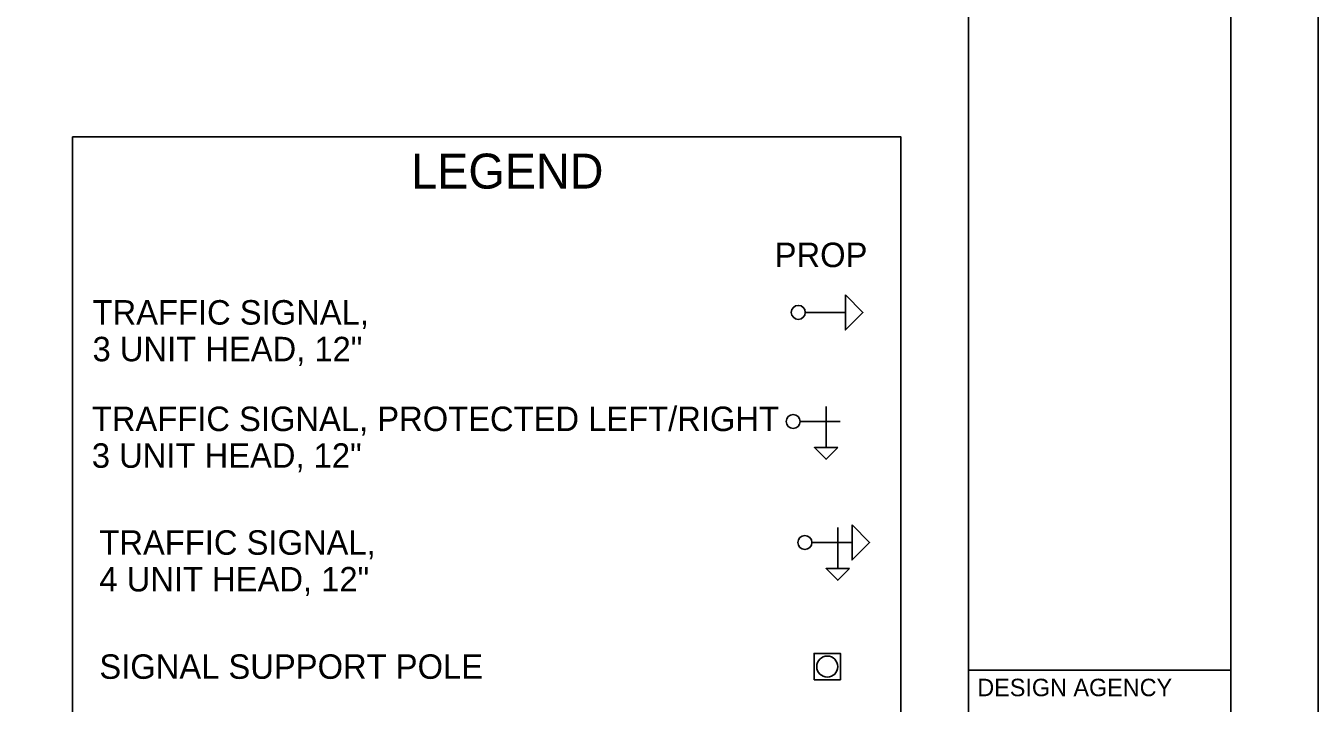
# Model space of a CAD drawing. Extents: x 0 to 34, y 0 to 22.
# Drawn here: x 26.61 to 34, y 4.31 to 8.19 of the extents above; entities that cross this region are included whole.
import ezdxf

# ---------------------------------------------------------------- set-up
doc = ezdxf.new("R2010")
doc.units = 0
for name, color, linetype in [('PM_P_Stop_Line', 7, 'Continuous'), ('SC_Scratch1', 7, 'Continuous'), ('SG_P_Detection', 7, 'Continuous'), ('SG_P_Heads', 7, 'Continuous'), ('UT_X_Electric', 7, 'Continuous')]:
    doc.layers.add(name, color=color, linetype=linetype)

msp = doc.modelspace()

# ---------------------------------------------------------------- linework, layer by layer
at = {"layer": 'PM_P_Stop_Line'}
for p, q in [((32, 0.5), (32, 21.5)), ((32, 4.5), (33.5, 4.5))]:
    msp.add_line(p, q, dxfattribs=at)
msp.add_lwpolyline([(1.5, 21.5), (33.5, 21.5), (33.5, 0.5), (1.5, 0.5)], close=True, dxfattribs=at)
at = {"layer": 'SC_Scratch1'}
msp.add_lwpolyline([(26.8738, 7.5516), (26.8738, 0.8263), (31.6119, 0.8263), (31.612, 7.5516), (31.612, 7.5516)], close=True, dxfattribs=at)
at = {"layer": 'SG_P_Detection'}
for p, q in [((31.1856, 6.0076), (31.1849, 5.7726)), ((31.0361, 5.9223), (31.2661, 5.9215))]:
    msp.add_line(p, q, dxfattribs=at)
msp.add_lwpolyline([(31.2513, 5.7727), (31.1844, 5.7062), (31.1179, 5.7731)], close=True, dxfattribs=at)
msp.add_circle((30.9961, 5.9224), 0.04, dxfattribs=at)
at = {"layer": 'SG_P_Heads'}
msp.add_lwpolyline([(0, 0), (34, 0), (34, 22), (0, 22)], close=True, dxfattribs=at)
at = {"layer": 'UT_X_Electric'}
for p, q in [((31.0658, 6.5467), (31.2958, 6.5467)), ((31.2528, 5.3154), (31.2528, 5.0804)), ((31.1036, 5.2295), (31.3336, 5.2295))]:
    msp.add_line(p, q, dxfattribs=at)
for points in [[(31.2957, 6.6466), (31.3957, 6.5466), (31.2957, 6.4466)], [(31.3331, 5.3299), (31.4331, 5.2299), (31.3331, 5.1299)], [(31.3184, 5.0807), (31.2518, 5.014), (31.1851, 5.0807)], [(31.1165, 4.4445), (31.2665, 4.4445), (31.2665, 4.5945), (31.1165, 4.5945)]]:
    msp.add_lwpolyline(points, close=True, dxfattribs=at)
for centre, radius in [((31.0258, 6.5467), 0.04), ((31.0636, 5.2295), 0.04), ((31.1915, 4.5195), 0.06)]:
    msp.add_circle(centre, radius, dxfattribs=at)

# ---------------------------------------------------------------- texts
at = {"layer": 'SC_Scratch1'}
msp.add_text('DESIGN AGENCY', height=0.1, dxfattribs=at).set_placement((32.05, 4.35))
at = {"layer": 'UT_X_Electric'}
for s, height, p in [('LEGEND', 0.2, (28.8111, 7.255)), ('PROP', 0.14, (30.8906, 6.8056)), ('TRAFFIC SIGNAL, ', 0.14, (26.9879, 6.4767)), ('3 UNIT HEAD, 12"', 0.14, (26.9879, 6.2667)), ('TRAFFIC SIGNAL, PROTECTED LEFT/RIGHT', 0.14, (26.9838, 5.8673)), ('3 UNIT HEAD, 12"', 0.14, (26.9838, 5.6573)), ('TRAFFIC SIGNAL,', 0.14, (27.0269, 5.1595)), ('4 UNIT HEAD, 12"', 0.14, (27.0269, 4.9495)), ('SIGNAL SUPPORT POLE', 0.14, (27.0269, 4.4495))]:
    msp.add_text(s, height=height, dxfattribs=at).set_placement(p)

doc.saveas('drawing.dxf')
